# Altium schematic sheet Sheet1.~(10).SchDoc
size A; SheetNumber: 1; SheetTotal: 1
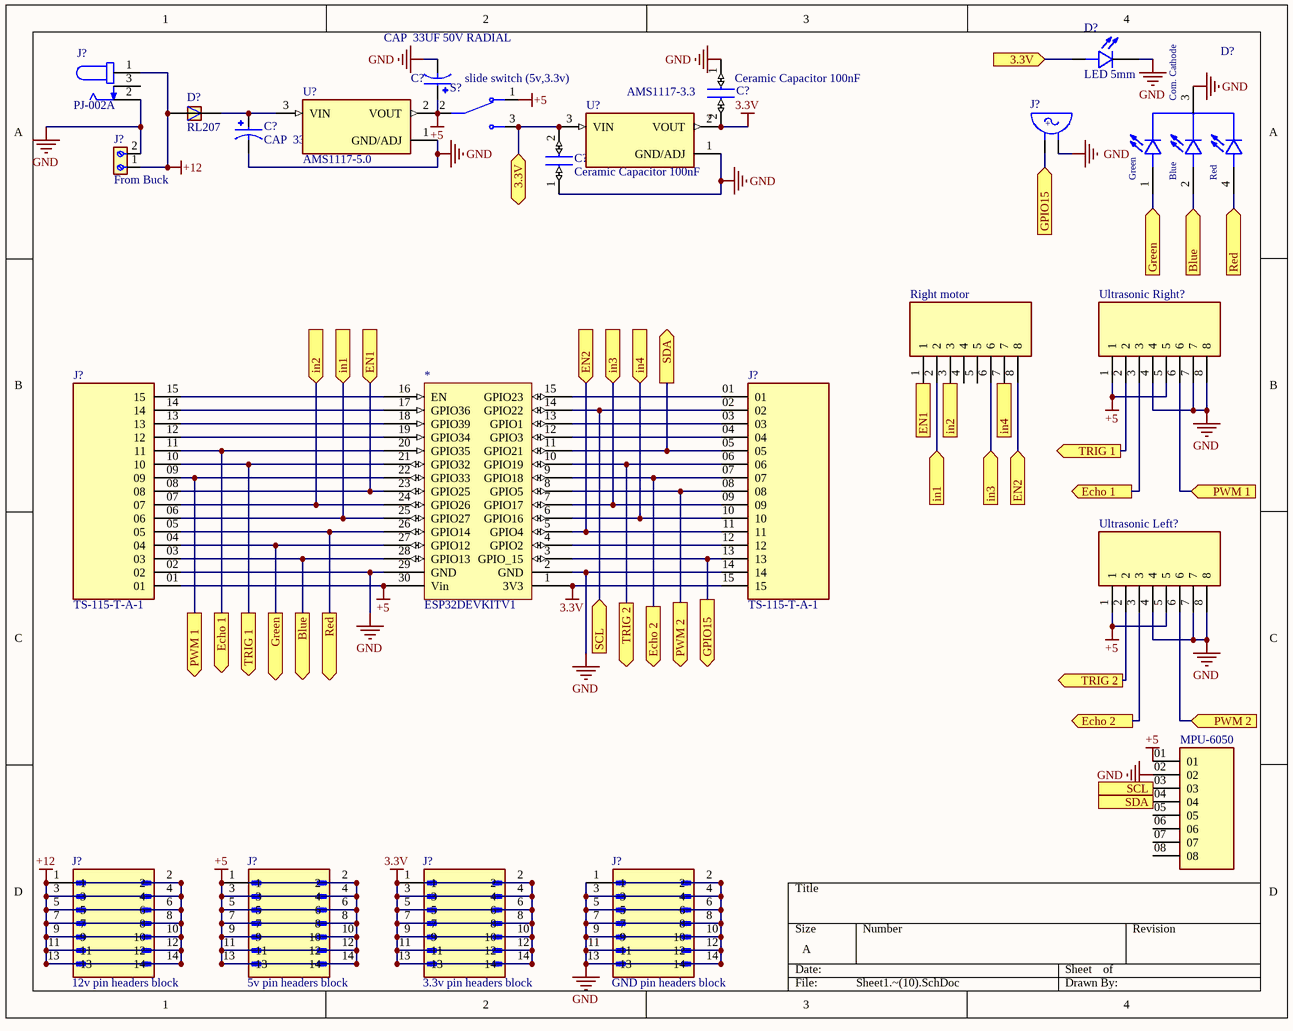
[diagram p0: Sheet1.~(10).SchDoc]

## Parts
(Parts that share a designator on the sheet are numbered #1, #2 ... from top to bottom, then left to right.)
*  ESP32DEVKITV1  [ESP32DEVKITV1]
C?#1  Ceramic Capacitor 100nF  [C320C]
C?#2  CAP  33UF 50V RADIAL  [CAP  33UF 50V RADIAL]
C?#3  CAP  33UF 50V RADIAL  [CAP  33UF 50V RADIAL]
C?#4  Ceramic Capacitor 100nF  [C320C]
D?#1  LED 5mm  [LED 5mm]
D?#2  RL207  [DIOAD1300W80L670D310]
D?#3  common cathode  [LED RGB 5mm]  (value not drawn)
J?#1  PJ-002A  [CUI_PJ-002A]
J?#2  WST-1205S  [WST-1205S]  (value not drawn)
J?#3  From Buck  [691213510002]
J?#4  TS-115-T-A-1  [SAMTEC_TS-115-T-A-1]
J?#5  TS-115-T-A-1  [SAMTEC_TS-115-T-A-1]
J?#6  12v pin headers block  [AMPHENOL_52601-S14-4LF]
J?#7  5v pin headers block  [AMPHENOL_52601-S14-4LF]
J?#8  3.3v pin headers block  [AMPHENOL_52601-S14-4LF]
J?#9  GND pin headers block  [AMPHENOL_52601-S14-4LF]
MPU-6050  8 Pins Headers  [SAMTEC_TS-108-X-A-1]  (value not drawn)
Right_motor  Pin header female block 8 pin  [Pin header female block 8 pin]  (value not drawn)
S?  slide switch (5v,3.3v)  [SW_EG1206]
U?#1  AMS1117-5.0  [SOT229P700X180-4N]
U?#2  AMS1117-3.3  [SOT229P700X180-4N]
Ultrasonic_Left?  Pin header female block 8 pin  [Pin header female block 8 pin]  (value not drawn)
Ultrasonic_Right?  Pin header female block 8 pin  [Pin header female block 8 pin]  (value not drawn)

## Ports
3.3V (bidir, see Sheet1[4A]), 3.3V (in, see Sheet1[2A]), Blue (in, see Sheet1[1C]), Blue (out, see Sheet1[4B]), Echo 1 (out, see Sheet1[1C]), Echo 1 (out, see Sheet1[4B]), Echo 2 (out, see Sheet1[3C]), Echo 2 (out, see Sheet1[4C]), EN1 (in, see Sheet1[2B]), EN1 (in, see Sheet1[3B]), EN2 (in, see Sheet1[2B]), EN2 (in, see Sheet1[4B]), GPIO15 (in, see Sheet1[3C]), GPIO15 (out, see Sheet1[4A]), Green (in, see Sheet1[1C]), Green (out, see Sheet1[4B]), in1 (in, see Sheet1[2B]), in1 (in, see Sheet1[3B]), in2 (in, see Sheet1[1B]), in2 (in, see Sheet1[3B]), in3 (in, see Sheet1[2B]), in3 (in, see Sheet1[4B]), in4 (in, see Sheet1[2B]), in4 (in, see Sheet1[4B]), PWM 1 (in, see Sheet1[1C]), PWM 1 (out, see Sheet1[4B]), PWM 2 (in, see Sheet1[3C]), PWM 2 (out, see Sheet1[4C]), Red (in, see Sheet1[2C]), Red (out, see Sheet1[4B]), SCL (in, see Sheet1[4D]), SCL (out, see Sheet1[2C]), SDA (out, see Sheet1[3B]), SDA (out, see Sheet1[4D]), TRIG 1 (out, see Sheet1[1C]), TRIG 1 (out, see Sheet1[4B]), TRIG 2 (out, see Sheet1[2C]), TRIG 2 (out, see Sheet1[4C])

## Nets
3.3V: *.1(3V3) C?#1.2 J?#5.15 J?#8.1 J?#8.2 J?#8.3 J?#8.4 J?#8.5 J?#8.6 J?#8.7 J?#8.8 J?#8.9 J?#8.10 J?#8.11 J?#8.12 J?#8.13 J?#8.14 U?#2.2(VOUT)
 GND: *.2(GND) *.29(GND) C?#1.1 C?#2.N C?#3.N C?#4.1 D?#1.C D?#3.3(Com._Cathode) J?#1.2 J?#2.NEG J?#3.2 J?#4.02 J?#5.14 J?#9.1 J?#9.2 J?#9.3 J?#9.4 J?#9.5 J?#9.6 J?#9.7 J?#9.8 J?#9.9 J?#9.10 J?#9.11 J?#9.12 J?#9.13 J?#9.14 MPU-6050.02 U?#1.1(GND/ADJ) U?#2.1(GND/ADJ) Ultrasonic_Left?.4 Ultrasonic_Left?.7 Ultrasonic_Left?.8 Ultrasonic_Right?.4 Ultrasonic_Right?.7 Ultrasonic_Right?.8  [also labelled GND]
+5: *.30(Vin) C?#2.P J?#4.01 J?#7.1 J?#7.2 J?#7.3 J?#7.4 J?#7.5 J?#7.6 J?#7.7 J?#7.8 J?#7.9 J?#7.10 J?#7.11 J?#7.12 J?#7.13 J?#7.14 MPU-6050.01 S?.1 S?.2 U?#1.2(VOUT) Ultrasonic_Left?.1 Ultrasonic_Left?.5 Ultrasonic_Right?.1 Ultrasonic_Right?.5
+12: D?#2.A J?#1.1 J?#3.1 J?#6.1 J?#6.2 J?#6.3 J?#6.4 J?#6.5 J?#6.6 J?#6.7 J?#6.8 J?#6.9 J?#6.10 J?#6.11 J?#6.12 J?#6.13 J?#6.14
3.3V: C?#4.2 D?#1.A S?.3 U?#2.3(VIN) ; port 3.3V  [a separate net that carries the same name]
Blue: *.28(GPIO13) D?#3.2(BLUE) J?#4.03 ; port Blue
Echo 1: *.20(GPIO35) J?#4.11 Ultrasonic_Right?.3 ; port Echo 1
Echo 2: *.9(GPIO18) J?#5.07 Ultrasonic_Left?.3 ; port Echo 2
EN1: *.23(GPIO25) J?#4.08 Right_motor.1 ; port EN1
EN2: *.5(GPIO4) J?#5.11 Right_motor.8 ; port EN2
GPIO15: *.3(GPIO_15) J?#2.POS J?#5.13 ; port GPIO15
Green: *.27(GPIO12) D?#3.1(Green) J?#4.04 ; port Green
in1: *.25(GPIO27) J?#4.06 Right_motor.2 ; port in1
in2: *.24(GPIO26) J?#4.07 Right_motor.3 ; port in2
in3: *.7(GPIO17) J?#5.09 Right_motor.6 ; port in3
in4: *.6(GPIO16) J?#5.10 Right_motor.7 ; port in4
PWM 1: *.22(GPIO33) J?#4.09 Ultrasonic_Right?.6 ; port PWM 1
PWM 2: *.8(GPIO5) J?#5.08 Ultrasonic_Left?.6 ; port PWM 2
Red: *.26(GPIO14) D?#3.4(Red) J?#4.05 ; port Red
SCL: *.14(GPIO22) J?#5.02 MPU-6050.03 ; port SCL
SDA: *.11(GPIO21) J?#5.05 MPU-6050.04 ; port SDA
TRIG 1: *.21(GPIO32) J?#4.10 Ultrasonic_Right?.2 ; port TRIG 1
TRIG 2: *.10(GPIO19) J?#5.06 Ultrasonic_Left?.2 ; port TRIG 2
Net*_4: *.4(GPIO2) J?#5.12
Net*_12: *.12(GPIO3) J?#5.04
Net*_13: *.13(GPIO1) J?#5.03
Net*_15: *.15(GPIO23) J?#5.01
Net*_16: *.16(EN) J?#4.15
Net*_17: *.17(GPIO36) J?#4.14
Net*_18: *.18(GPIO39) J?#4.13
Net*_19: *.19(GPIO34) J?#4.12
NetC?#3_P: C?#3.P D?#2.C U?#1.3(VIN)

Not connected (* = marked no-connect by the designer): J?#1 3; MPU-6050 05 06 07 08; Right_motor 4 5

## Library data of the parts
C?#1 C?#4 = Ceramic Capacitor 100nF: 0.1ÂµF Â±20% 50V Ceramic Capacitor Z5U Radial; MF: KEMET; MP: C320C104M5U5TA
C?#2 C?#3 = CAP  33UF 50V RADIAL: NHG-A; MF: {'manufacturer': u'Panasonic'}; MP: ECA1HHG330I
D?#1 = LED 5mm: Red 623nm LED Indication - Discrete 1.9V Radial; MF: {'manufacturer': u'Wurth Elektronik'}; MP: 151054RS03000
D?#2 = RL207: Semiconductors and Actives, Power Diodes, Discretes (diodes, transistors, thyristors ...), Diodes; MF: {'manufacturer': u'Diodes Inc.'}
D?#3 = LED RGB 5mm: MF: {'manufacturer': u'Kingbright'}; MP: WP154A4SUREQBFZGC
J?#1 = PJ-002A: 2.0 mm Center Pin, 2.5 A, Right Angle, Through Hole, Dc Power Jack Connector; MF: {'manufacturer': u'CUI Devices'}
J?#2 = WST-1205S: BUZZER 2.3KHZ 4-6VDC; MF: {'manufacturer': u'Soberton Inc.'}
J?#3 = Terminal Block: 2 Position Wire to Board Terminal Block Horizontal with Board 0.200 (5.08mm) Through Hole; MF: Wurth Electronics
J?#4 J?#5 = TS-115-T-A-1: MF: {'manufacturer': u'Samtec'}
J?#6-J?#9 = 52601-S14-4LF: MF: {'manufacturer': u'Amphenol ICC (FCI)'}
MPU-6050 = 8 Pins Headers: TS Series .100" Single Row Screw Machine Terminal Strip; MF: {'manufacturer': u'Samtec'}; MP: TS-108-X-A-1
Right_motor Ultrasonic_Left? Ultrasonic_Right? = Pin header female block 8 pin: MF: {'manufacturer': u'TE Connectivity'}; MP: 5-534998-4
S? = EG1206: MF: {'manufacturer': u'E-Switch'}
U?#1 = AMS1117-5.0: MF: {'manufacturer': u'Advanced Monolithic Systems'}
U?#2 = AMS1117-3.3: MF: {'manufacturer': u'Advanced Monolithic Systems'}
